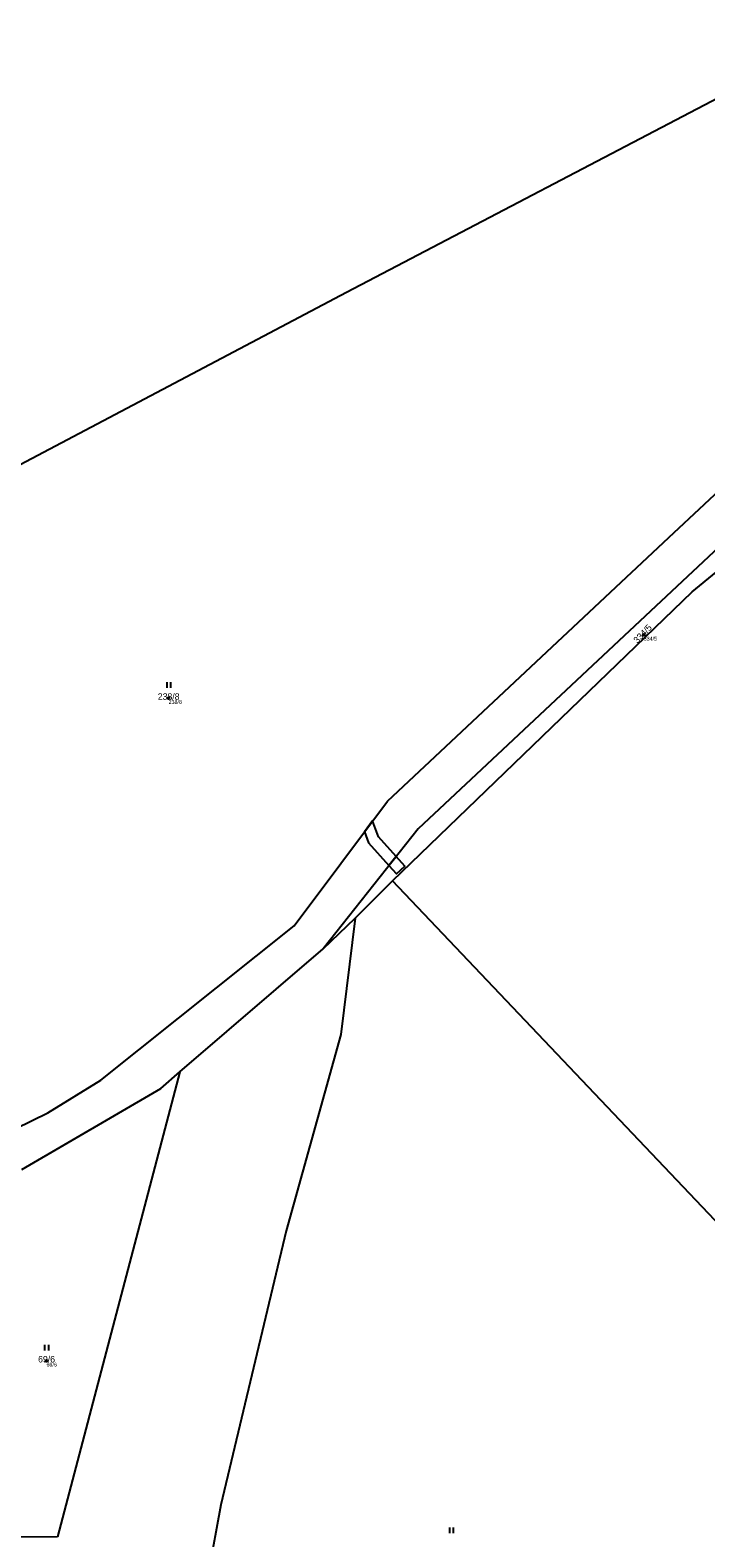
# Model space of a CAD drawing. Extents: x -868010 to -864567, y -1041968 to -1040406.
# Drawn here: x -865455 to -865278.2, y -1041393.5 to -1040999.3 of the extents above; entities that cross this region are included whole.
import ezdxf

# ---------------------------------------------------------------- set-up
doc = ezdxf.new("R2010")
doc.units = 0
for name, color, linetype in [('Definiční body', 7, 'Continuous'), ('Hranice parcel', 7, 'Continuous'), ('Parcelní čísla', 7, 'Continuous'), ('Věcná břemena k části', 7, 'Continuous'), ('Značky kultur', 7, 'Continuous')]:
    doc.layers.add(name, color=color, linetype=linetype)

msp = doc.modelspace()

# ---------------------------------------------------------------- linework, layer by layer
at = {"layer": 'Definiční body'}
for centre in [(-865294.4, -1041157.44994), (-865418.73, -1041173.98994), (-865450.68, -1041347.25994)]:
    msp.add_circle(centre, 0.25, dxfattribs=at)
at = {"layer": 'Hranice parcel'}
for p, q in [((-865241.11, -1040999.33), (-865372.19, -1041067.89)), ((-865287.85, -1041131.96), (-865212.49, -1041061.43)), ((-865372.19, -1041067.89), (-865546.43, -1041159.8)), ((-865267.75, -1041127.94), (-865353.48, -1041208.17)), ((-865361.5, -1041200.89), (-865287.85, -1041131.96)), ((-865281.73, -1041146.19), (-865261.91, -1041129.94)), ((-865360.15, -1041221.77), (-865281.73, -1041146.19)), ((-865385.86, -1041233.55), (-865361.5, -1041200.89)), ((-865353.48, -1041208.17), (-865378.27, -1041239.56)), ((-865369.89, -1041231.51), (-865360.15, -1041221.77)), ((-865257.42, -1041329.82), (-865360.15, -1041221.77)), ((-865436.48, -1041273.87), (-865385.86, -1041233.55)), ((-865378.27, -1041239.56), (-865369.89, -1041231.51)), ((-865369.89, -1041231.51), (-865373.69, -1041261.93)), ((-865415.84, -1041271.68), (-865378.27, -1041239.56)), ((-865373.69, -1041261.93), (-865387.98, -1041313.26)), ((-865450.38, -1041282.41), (-865436.48, -1041273.87)), ((-865415.84, -1041271.68), (-865447.81, -1041393.26)), ((-865420.8, -1041276.05), (-865415.84, -1041271.68)), ((-865457.18, -1041297.23), (-865420.8, -1041276.05)), ((-865463.09, -1041288.56), (-865450.38, -1041282.41)), ((-865387.98, -1041313.26), (-865405.09, -1041384.92)), ((-865405.09, -1041384.92), (-865418.07, -1041456.71)), ((-865447.81, -1041393.26), (-865476.55, -1041393.41))]:
    msp.add_line(p, q, dxfattribs=at)
at = {"layer": 'Věcná břemena k části'}
for points in [[(-865363.82, -1041210.28), (-865365.38, -1041206.09), (-865367.51, -1041208.95), (-865366.43, -1041211.86), (-865361.07, -1041217.78), (-865359.19, -1041215.4)], [(-865359.19, -1041215.4), (-865361.07, -1041217.78), (-865359.11, -1041219.94), (-865356.89, -1041217.93)]]:
    msp.add_lwpolyline(points, close=True, dxfattribs=at)
at = {"layer": 'Značky kultur'}
for p, q in [((-865419.131, -1041171.29), (-865419.131, -1041169.79)), ((-865418.13, -1041171.29), (-865418.13, -1041169.79)), ((-865451.091, -1041344.56), (-865451.091, -1041343.06)), ((-865450.09, -1041344.56), (-865450.09, -1041343.06)), ((-865345.191, -1041392.33), (-865345.191, -1041390.83)), ((-865344.19, -1041392.33), (-865344.19, -1041390.83))]:
    msp.add_line(p, q, dxfattribs=at)

# ---------------------------------------------------------------- texts
at = {"layer": 'Definiční body'}
for s, p in [('334/5', (-865294.4, -1041158.939)), ('238/8', (-865418.73, -1041175.479)), ('69/6', (-865450.68, -1041348.749))]:
    msp.add_text(s, height=0.999996, dxfattribs=at).set_placement(p)
at = {"layer": 'Parcelní čísla'}
msp.add_text('334/5', height=1.699998, rotation=46, dxfattribs=at).set_placement((-865296.064, -1041159.785))
for s, p in [('238/8', (-865421.566, -1041174.415)), ('69/6', (-865452.885, -1041347.685))]:
    msp.add_text(s, height=1.699998, dxfattribs=at).set_placement(p)

doc.saveas('drawing.dxf')
